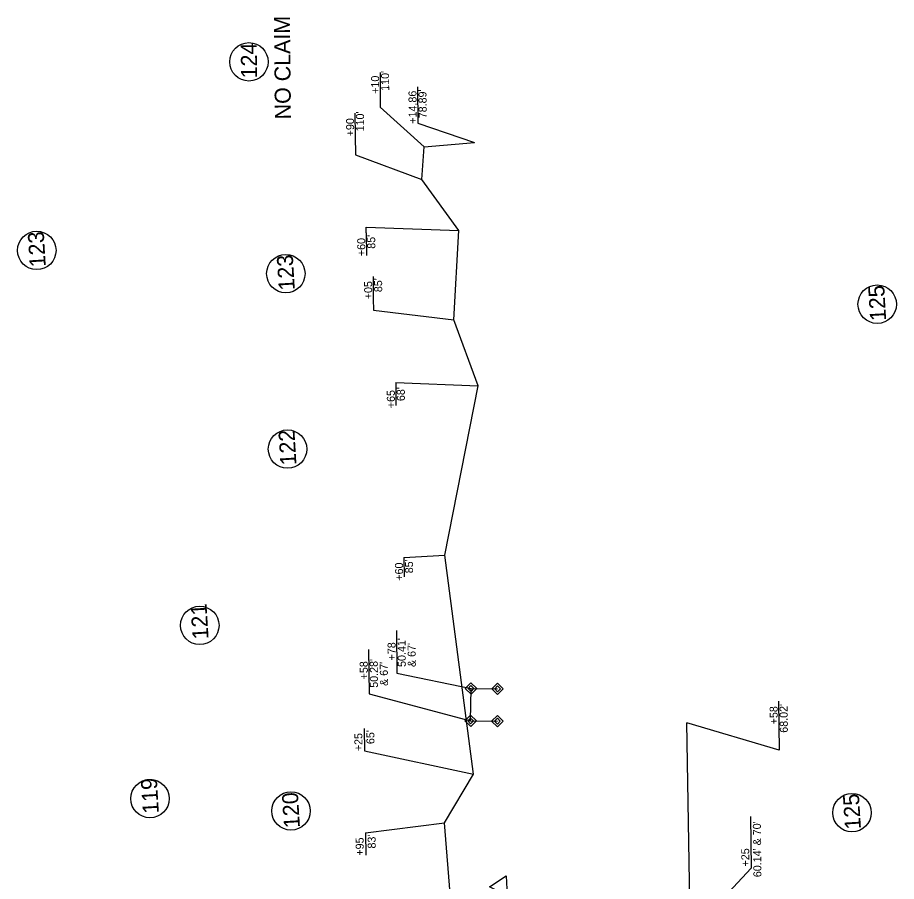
# Model space of a CAD drawing. Extents: x 2320946 to 2332748, y 597838 to 612698.
# Drawn here: x 2328035 to 2328584, y 605414 to 605954 of the extents above; entities that cross this region are included whole.
import ezdxf

# ---------------------------------------------------------------- set-up
doc = ezdxf.new("R2010")
doc.units = 0
for name, color, linetype in [('Prop Easement Construction', 7, 'Continuous'), ('Prop Easement Construction Station Offsets', 7, 'Continuous'), ('Prop Easement Permanent Drainage', 7, 'Continuous'), ('Prop Easement Permanent Drainage Station Offsets', 7, 'Continuous'), ('Prop Parcel Number CELL', 7, 'Continuous'), ('Prop ROW Marker CELL', 7, 'Continuous'), ('Prop ROW Permanent Easement CELL', 7, 'Continuous')]:
    doc.layers.add(name, color=color, linetype=linetype)

msp = doc.modelspace()

# ---------------------------------------------------------------- linework, layer by layer
at = {"layer": 'Prop Easement Construction'}
for p, q in [((2328288.88, 605872.92), (2328320.25, 605875.71)), ((2328287.52, 605852.6), (2328288.88, 605872.92)), ((2328310.57, 605820.61), (2328287.52, 605852.6)), ((2328455.12, 605381.61), (2328452.93, 605513.08)), ((2328307.12, 605380.76), (2328301.65, 605450.65))]:
    msp.add_line(p, q, dxfattribs=at)
for points in [[(2328322.54, 605723.64), (2328307.48, 605764.91), (2328310.57, 605820.61)], [(2328301.65, 605450.65), (2328319.69, 605480.99), (2328301.79, 605617.97), (2328322.54, 605723.64)]]:
    msp.add_lwpolyline(points, dxfattribs=at)
at = {"layer": 'Prop Easement Construction Station Offsets'}
for p, q in [((2328261.35, 605919.34), (2328261.46, 605906.38)), ((2328284.68, 605910.51), (2328284.88, 605887.76)), ((2328245.71, 605893.99), (2328245.83, 605879.83)), ((2328252.67, 605819.14), (2328252.8, 605804.98)), ((2328256.99, 605792.02), (2328257.11, 605778.02)), ((2328271.15, 605725.67), (2328271.28, 605711.37)), ((2328276.26, 605616.42), (2328276.37, 605604.42)), ((2328510.2, 605526.69), (2328510.49, 605496)), ((2328510.49, 605496), (2328452.93, 605513.08)), ((2328251.5, 605509.71), (2328251.64, 605495.71)), ((2328252.31, 605444.48), (2328252.45, 605430.48))]:
    msp.add_line(p, q, dxfattribs=at)
for points in [[(2328261.46, 605906.38), (2328261.53, 605897.66), (2328288.88, 605872.92)], [(2328284.88, 605887.76), (2328320.25, 605875.71)], [(2328245.83, 605879.83), (2328245.93, 605867.98), (2328287.52, 605852.6)], [(2328252.67, 605819.14), (2328252.64, 605822.84), (2328310.57, 605820.61)], [(2328257.11, 605778.02), (2328257.17, 605770.98), (2328307.48, 605764.91)], [(2328271.15, 605725.67), (2328322.54, 605723.64)], [(2328276.26, 605616.42), (2328301.79, 605617.97)], [(2328251.64, 605495.71), (2328319.69, 605480.99)], [(2328252.31, 605444.48), (2328301.65, 605450.65)]]:
    msp.add_lwpolyline(points, dxfattribs=at)
at = {"layer": 'Prop Easement Permanent Drainage'}
for p, q in [((2328317.92, 605514.37), (2328318.15, 605534.59)), ((2328318.15, 605534.59), (2328334.73, 605534.38)), ((2328317.92, 605514.37), (2328334.64, 605514.21))]:
    msp.add_line(p, q, dxfattribs=at)
at = {"layer": 'Prop Easement Permanent Drainage Station Offsets'}
for p, q in [((2328271.59, 605570.77), (2328271.84, 605544.15)), ((2328254.21, 605558.96), (2328254.48, 605531.23)), ((2328492.71, 605454.6), (2328493.01, 605422.43)), ((2328493.01, 605422.43), (2328455.12, 605381.61))]:
    msp.add_line(p, q, dxfattribs=at)
for points in [[(2328271.84, 605544.15), (2328318.15, 605534.59)], [(2328254.48, 605531.23), (2328317.92, 605514.37)]]:
    msp.add_lwpolyline(points, dxfattribs=at)
at = {"layer": 'Prop Parcel Number CELL'}
for p, q in [((2328179.48, 605926.03), (2328179.48, 605926.03)), ((2328047.01, 605808.22), (2328047.01, 605808.22)), ((2328202.52, 605793.73), (2328202.52, 605793.73)), ((2328571.8, 605774.64), (2328571.8, 605774.64)), ((2328203.57, 605684.14), (2328203.57, 605684.14)), ((2328148.79, 605574.01), (2328148.79, 605574.01)), ((2328117.69, 605465.82), (2328117.69, 605465.82)), ((2328205.73, 605458.11), (2328205.73, 605458.11)), ((2328556.05, 605457.04), (2328556.05, 605457.04))]:
    msp.add_line(p, q, dxfattribs=at)
for centre in [(2328179.48, 605926.03), (2328047.01, 605808.22), (2328202.52, 605793.73), (2328571.8, 605774.64), (2328203.57, 605684.14), (2328148.79, 605574.01), (2328117.69, 605465.82), (2328205.73, 605458.11), (2328556.05, 605457.04)]:
    msp.add_circle(centre, 12, dxfattribs=at)
at = {"layer": 'Prop ROW Marker CELL'}
for p, q in [((2328318.15, 605534.59), (2328318.15, 605534.59)), ((2328334.73, 605534.38), (2328334.73, 605534.38)), ((2328317.92, 605514.37), (2328317.92, 605514.37)), ((2328334.64, 605514.21), (2328334.64, 605514.21))]:
    msp.add_line(p, q, dxfattribs=at)
msp.add_lwpolyline([(2328340.78, 605405.08), (2328329.63, 605410.67), (2328340.03, 605417.56)], close=True, dxfattribs=at)
at = {"layer": 'Prop ROW Permanent Easement CELL'}
for points in [[(2328314.55, 605534.55), (2328318.11, 605538.19), (2328321.75, 605534.62), (2328318.18, 605530.99)], [(2328316.35, 605534.57), (2328318.13, 605536.39), (2328319.95, 605534.61), (2328318.17, 605532.79)], [(2328331.13, 605534.34), (2328334.7, 605537.97), (2328338.33, 605534.41), (2328334.77, 605530.78)], [(2328332.93, 605534.36), (2328334.72, 605536.17), (2328336.53, 605534.39), (2328334.75, 605532.58)], [(2328314.32, 605514.33), (2328317.89, 605517.97), (2328321.52, 605514.4), (2328317.96, 605510.77)], [(2328316.12, 605514.35), (2328317.9, 605516.17), (2328319.72, 605514.38), (2328317.94, 605512.57)], [(2328331.04, 605514.17), (2328334.6, 605517.81), (2328338.24, 605514.24), (2328334.67, 605510.61)], [(2328332.84, 605514.19), (2328334.62, 605516.01), (2328336.44, 605514.22), (2328334.65, 605512.41)]]:
    msp.add_lwpolyline(points, close=True, dxfattribs=at)

# ---------------------------------------------------------------- texts
at = {"layer": 'Prop Easement Construction Station Offsets'}
for s, rotation, p in [("110'", 90.5004, (2328267.07, 605907.95)), ('+10', 90.5004, (2328260.84, 605906.08)), ('+14.86', 90.5004, (2328284.26, 605887.39)), ("78.89'", 90.5004, (2328290.48, 605890.79)), ("110'", 90.5004, (2328251.43, 605882.59)), ('+90', 90.5004, (2328245.21, 605879.53)), ('+60', 90.5004, (2328252.18, 605804.68)), ("85'", 90.5004, (2328258.39, 605809.3)), ('+05', 90.5004, (2328256.48, 605777.76)), ("85'", 90.5004, (2328262.7, 605782.19)), ("68'", 90.5488, (2328276.88, 605714.15)), ('+65', 90.5488, (2328270.67, 605709.72)), ('+60', 90.5488, (2328275.77, 605601.96)), ("85'", 90.5488, (2328281.98, 605606.59)), ("68.02'", 90.5483, (2328516.01, 605506.98)), ('+58', 90.5483, (2328509.71, 605512.24)), ("65'", 90.5488, (2328257.85, 605499.89)), ('+25', 90.5488, (2328250.39, 605495.45)), ('+95', 90.5488, (2328251.2, 605430.22)), ("83'", 90.5488, (2328258.66, 605434.66))]:
    msp.add_text(s, height=5, rotation=rotation, dxfattribs=at).set_placement(p)
at = {"layer": 'Prop Easement Permanent Drainage Station Offsets'}
for s, rotation, p in [('+78', 90.5483, (2328271.14, 605552.15)), ("50.41'", 90.5483, (2328277.43, 605548.08)), ("& 67'", 90.5483, (2328283.68, 605548.04)), ('+58', 90.5483, (2328253.77, 605540.33)), ("50.28'", 90.5483, (2328260.07, 605535.07)), ("& 67'", 90.5483, (2328266.31, 605536.23)), ("60.14' & 70'", 90.5488, (2328499.49, 605416.77)), ('+25', 90.5488, (2328491.98, 605423.47))]:
    msp.add_text(s, height=5, rotation=rotation, dxfattribs=at).set_placement(p)
at = {"layer": 'Prop Parcel Number CELL'}
for s, rotation, p in [('NO CLAIM', 90.5471, (2328205.71, 605890.14)), ('124', 90.5471, (2328184.58, 605915.77)), ('123', 93.4368, (2328052.63, 605798.09)), ('123', 93.4368, (2328208.14, 605783.6)), ('125', 93.4368, (2328577.42, 605764.49)), ('122', 93.4368, (2328209.17, 605674.33)), ('121', 93.4368, (2328154.3, 605565.64)), ('119', 93.4368, (2328123.25, 605456.75)), ('120', 93.4368, (2328211.36, 605447.76)), ('125', 93.4368, (2328561.67, 605446.89))]:
    msp.add_text(s, height=10, rotation=rotation, dxfattribs=at).set_placement(p)

doc.saveas('drawing.dxf')
